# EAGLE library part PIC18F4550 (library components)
PIC18F4550 DIP-40 Specially arranged for schematics for the Yaesu FT-757GX Enhanced CAT interface schematics.
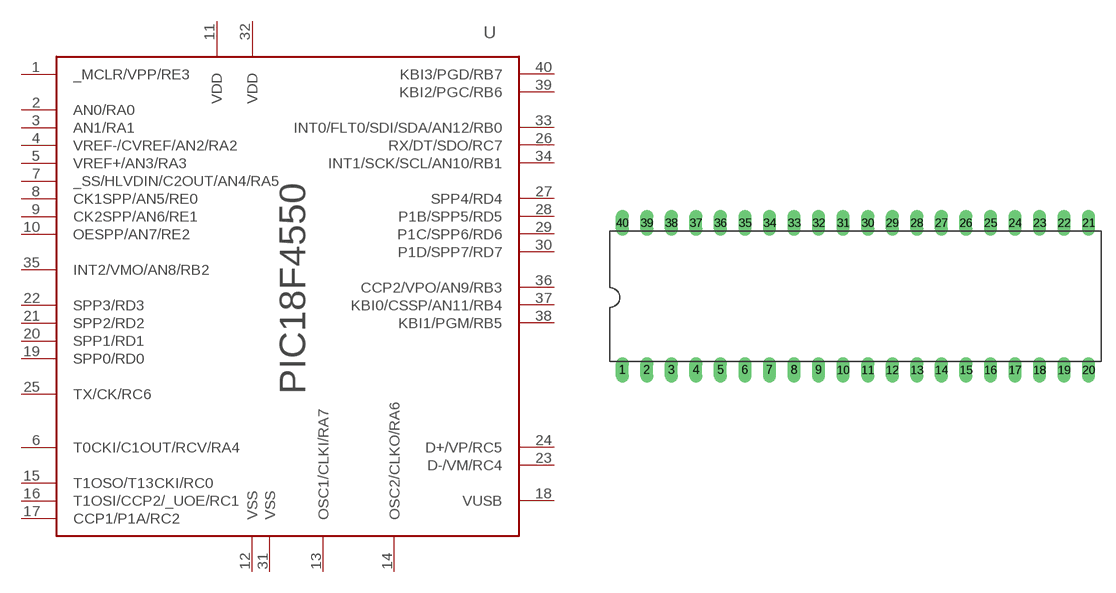
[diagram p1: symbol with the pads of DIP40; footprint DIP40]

Designator prefix -

## PIC18F4550  [DIP40]
1  _MCLR/VPP/RE3  in
2  AN0/RA0
3  AN1/RA1
4  VREF-/CVREF/AN2/RA2
5  VREF+/AN3/RA3
6  T0CKI/C1OUT/RCV/RA4
7  _SS/HLVDIN/C2OUT/AN4/RA5
8  CK1SPP/AN5/RE0
9  CK2SPP/AN6/RE1
10  OESPP/AN7/RE2
11  VDD  pwr
12  VSS  pwr
13  OSC1/CLKI/RA7
14  OSC2/CLKO/RA6
15  T1OSO/T13CKI/RC0
16  T1OSI/CCP2/_UOE/RC1
17  CCP1/P1A/RC2
18  VUSB
19  SPP0/RD0
20  SPP1/RD1
21  SPP2/RD2
22  SPP3/RD3
23  D-/VM/RC4
24  D+/VP/RC5
25  TX/CK/RC6
26  RX/DT/SDO/RC7
27  SPP4/RD4
28  P1B/SPP5/RD5
29  P1C/SPP6/RD6
30  P1D/SPP7/RD7
31  VSS  pwr
32  VDD  pwr
33  INT0/FLT0/SDI/SDA/AN12/RB0
34  INT1/SCK/SCL/AN10/RB1
35  INT2/VMO/AN8/RB2
36  CCP2/VPO/AN9/RB3
37  KBI0/CSSP/AN11/RB4
38  KBI1/PGM/RB5
39  KBI2/PGC/RB6
40  KBI3/PGD/RB7

## Footprint DIP40 (pad centres in mm)
drill 0.813 long: 1 -24.13,-8.89; 2 -21.59,-8.89; 3 -19.05,-8.89; 4 -16.51,-8.89; 5 -13.97,-8.89; 6 -11.43,-8.89; 7 -8.89,-8.89; 8 -6.35,-8.89; 9 -3.81,-8.89; 10 -1.27,-8.89; 11 1.27,-8.89; 12 3.81,-8.89; 13 6.35,-8.89; 14 8.89,-8.89; 15 11.43,-8.89; 16 13.97,-8.89; 17 16.51,-8.89; 18 19.05,-8.89; 19 21.59,-8.89; 20 24.13,-8.89; 21 24.13,6.35; 22 21.59,6.35; 23 19.05,6.35; 24 16.51,6.35; 25 13.97,6.35; 26 11.43,6.35; 27 8.89,6.35; 28 6.35,6.35; 29 3.81,6.35; 30 1.27,6.35; 31 -1.27,6.35; 32 -3.81,6.35; 33 -6.35,6.35; 34 -8.89,6.35; 35 -11.43,6.35; 36 -13.97,6.35; 37 -16.51,6.35; 38 -19.05,6.35; 39 -21.59,6.35; 40 -24.13,6.35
